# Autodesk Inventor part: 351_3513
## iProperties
Author: tomm
Created: 2002-01
Part Number: 351_3513
Material: Steel, Mild
Document SubType Name: Modeling
Designer: tomm
Control State: 0
Master: False
Checked Out: False
Last Check In Date: 2002-01-29
PropertySet Name: Design Tracking Control
Last Check In By: tomm
Shininess: 70.0
PropertySet Name: _Private Model Information
Density: 7.859999999999999
Volume: 0.6154241944495848
Area: 5.732774810185711
PropertySet Name: Model Information
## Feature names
1. Base1
